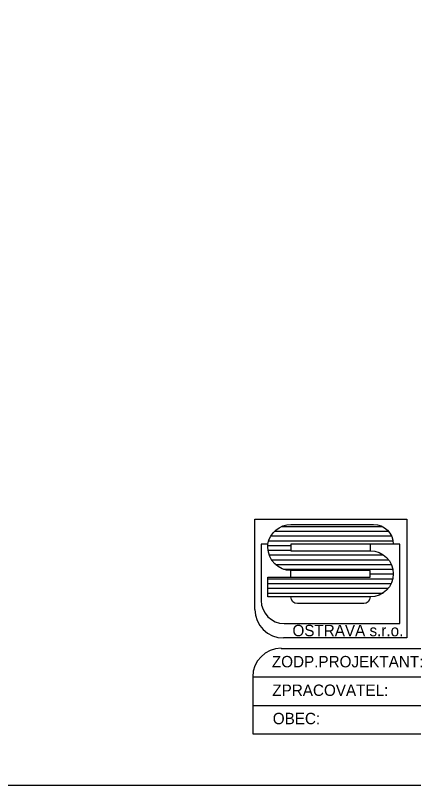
# Model space of a CAD drawing. Extents: x -557942 to -541772, y -1047288 to -1036007.
# Drawn here: x -556692 to -556272, y -1042803 to -1041993 of the extents above; entities that cross this region are included whole.
import ezdxf

# ---------------------------------------------------------------- set-up
doc = ezdxf.new("R2010")
doc.units = 0
doc.layers.add('Vrstva 1', color=7, linetype='Continuous')

msp = doc.modelspace()

# ---------------------------------------------------------------- linework, layer by layer
at = {"layer": 'Vrstva 1'}
for p, q in [((-556418.69, -1042535.45), (-556298.97, -1042535.45)), ((-556418.69, -1042535.45), (-556298.97, -1042535.45)), ((-556411.36, -1042530.45), (-556305.45, -1042530.45)), ((-556411.36, -1042530.45), (-556305.45, -1042530.45)), ((-556422.71, -1042540.45), (-556295.66, -1042540.45)), ((-556422.71, -1042540.45), (-556295.66, -1042540.45)), ((-556425.77, -1042550.45), (-556401.53, -1042550.45)), ((-556425.77, -1042550.45), (-556401.53, -1042550.45)), ((-556424.89, -1042545.45), (-556294.09, -1042545.45)), ((-556424.89, -1042545.45), (-556294.09, -1042545.45)), ((-556425.55, -1042555.45), (-556401.53, -1042555.45)), ((-556425.55, -1042555.45), (-556401.53, -1042555.45)), ((-556424.42, -1042560.45), (-556304.06, -1042560.45)), ((-556424.42, -1042560.45), (-556304.06, -1042560.45)), ((-556422.01, -1042565.45), (-556298.9, -1042565.45)), ((-556422.01, -1042565.45), (-556298.9, -1042565.45)), ((-556417.82, -1042570.45), (-556295.9, -1042570.45)), ((-556417.82, -1042570.45), (-556295.9, -1042570.45)), ((-556409.49, -1042575.45), (-556294.24, -1042575.45)), ((-556409.49, -1042575.45), (-556294.24, -1042575.45)), ((-556425.83, -1042585.45), (-556294.32, -1042585.45)), ((-556425.83, -1042585.45), (-556294.32, -1042585.45)), ((-556318.06, -1042580.45), (-556293.77, -1042580.45)), ((-556318.06, -1042580.45), (-556293.77, -1042580.45)), ((-556425.83, -1042590.45), (-556296.04, -1042590.45)), ((-556425.83, -1042590.45), (-556296.04, -1042590.45)), ((-556425.83, -1042595.45), (-556299.16, -1042595.45)), ((-556425.83, -1042595.45), (-556299.16, -1042595.45)), ((-556425.83, -1042600.45), (-556304.37, -1042600.45)), ((-556425.83, -1042600.45), (-556304.37, -1042600.45)), ((-556411.84, -1042658.67), (-555561.84, -1042658.67)), ((-556411.84, -1042658.67), (-555561.84, -1042658.67)), ((-556441.84, -1042688.67), (-555561.84, -1042688.67)), ((-556441.84, -1042688.67), (-556441.84, -1042748.67)), ((-556441.84, -1042688.67), (-555561.84, -1042688.67)), ((-556441.84, -1042688.67), (-556441.84, -1042748.67)), ((-556441.84, -1042718.67), (-555561.84, -1042718.67)), ((-556441.84, -1042718.67), (-555561.84, -1042718.67)), ((-556441.84, -1042748.67), (-555561.84, -1042748.67)), ((-556441.84, -1042748.67), (-555561.84, -1042748.67))]:
    msp.add_line(p, q, dxfattribs=at)
msp.add_lwpolyline([(-555441.84, -1039561.93), (-555441.84, -1042803.07), (-557941.84, -1042803.07), (-557941.84, -1039561.93)], close=True, dxfattribs=at)
for points in [[(-556439.45, -1042617.77), (-556439.45, -1042522.77), (-556279.45, -1042522.77), (-556279.45, -1042647.77), (-556409.45, -1042647.77)], [(-556439.45, -1042617.77), (-556439.45, -1042522.77), (-556279.45, -1042522.77), (-556279.45, -1042647.77), (-556409.45, -1042647.77)], [(-556318.06, -1042549.17), (-556401.53, -1042549.17), (-556401.53, -1042556.02), (-556318.06, -1042556.02), (-556313.1, -1042556.5), (-556308.53, -1042557.93), (-556304.34, -1042560.22), (-556300.81, -1042563.17), (-556297.86, -1042566.7), (-556295.67, -1042570.89), (-556294.24, -1042575.46), (-556293.76, -1042580.32), (-556294.24, -1042585.18), (-556295.67, -1042589.76), (-556297.86, -1042593.85), (-556300.81, -1042597.47), (-556304.34, -1042600.43), (-556308.53, -1042602.72), (-556313.1, -1042604.14), (-556318.06, -1042604.62), (-556401.53, -1042604.62), (-556425.83, -1042604.62), (-556425.83, -1042583.85), (-556401.53, -1042583.85), (-556318.06, -1042583.85), (-556318.06, -1042576.89), (-556401.53, -1042576.89), (-556406.39, -1042576.42), (-556410.96, -1042574.99), (-556415.06, -1042572.7), (-556418.68, -1042569.75), (-556421.64, -1042566.13), (-556423.92, -1042562.03), (-556425.35, -1042557.45), (-556425.83, -1042552.59), (-556425.73, -1042548.97), (-556424.68, -1042544.59), (-556422.87, -1042540.68), (-556420.39, -1042537.16), (-556417.44, -1042534.2), (-556413.91, -1042531.73), (-556410.1, -1042529.82), (-556405.91, -1042528.68), (-556401.53, -1042528.3), (-556314.63, -1042528.3), (-556310.34, -1042528.68), (-556306.43, -1042529.92), (-556302.91, -1042531.82), (-556299.86, -1042534.39), (-556297.29, -1042537.44), (-556295.38, -1042540.97), (-556294.14, -1042544.88), (-556293.76, -1042549.17), (-556318.06, -1042549.17)], [(-556318.06, -1042549.17), (-556401.53, -1042549.17), (-556401.53, -1042556.02), (-556318.06, -1042556.02), (-556313.1, -1042556.5), (-556308.53, -1042557.93), (-556304.34, -1042560.22), (-556300.81, -1042563.17), (-556297.86, -1042566.7), (-556295.67, -1042570.89), (-556294.24, -1042575.46), (-556293.76, -1042580.32), (-556294.24, -1042585.18), (-556295.67, -1042589.76), (-556297.86, -1042593.85), (-556300.81, -1042597.47), (-556304.34, -1042600.43), (-556308.53, -1042602.72), (-556313.1, -1042604.14), (-556318.06, -1042604.62), (-556401.53, -1042604.62), (-556425.83, -1042604.62), (-556425.83, -1042583.85), (-556401.53, -1042583.85), (-556318.06, -1042583.85), (-556318.06, -1042576.89), (-556401.53, -1042576.89), (-556406.39, -1042576.42), (-556410.96, -1042574.99), (-556415.06, -1042572.7), (-556418.68, -1042569.75), (-556421.64, -1042566.13), (-556423.92, -1042562.03), (-556425.35, -1042557.45), (-556425.83, -1042552.59), (-556425.73, -1042548.97), (-556424.68, -1042544.59), (-556422.87, -1042540.68), (-556420.39, -1042537.16), (-556417.44, -1042534.2), (-556413.91, -1042531.73), (-556410.1, -1042529.82), (-556405.91, -1042528.68), (-556401.53, -1042528.3), (-556314.63, -1042528.3), (-556310.34, -1042528.68), (-556306.43, -1042529.92), (-556302.91, -1042531.82), (-556299.86, -1042534.39), (-556297.29, -1042537.44), (-556295.38, -1042540.97), (-556294.14, -1042544.88), (-556293.76, -1042549.17), (-556318.06, -1042549.17)], [(-556286.71, -1042632.54), (-556286.71, -1042549.07), (-556293.76, -1042549.07), (-556318.06, -1042549.07), (-556318.06, -1042556.02), (-556313.1, -1042556.5), (-556308.53, -1042557.93), (-556304.34, -1042560.22), (-556300.81, -1042563.17), (-556297.86, -1042566.7), (-556295.67, -1042570.89), (-556294.24, -1042575.46), (-556293.76, -1042580.32), (-556294.24, -1042585.18), (-556295.67, -1042589.76), (-556297.86, -1042593.85), (-556300.81, -1042597.47), (-556304.34, -1042600.43), (-556308.53, -1042602.72), (-556313.1, -1042604.14), (-556318.06, -1042604.62), (-556318.63, -1042607.38), (-556320.06, -1042609.58), (-556322.25, -1042611.1), (-556324.92, -1042611.67), (-556394.57, -1042611.67), (-556397.34, -1042611.1), (-556399.53, -1042609.58), (-556400.96, -1042607.38), (-556401.53, -1042604.62), (-556425.83, -1042604.62), (-556425.83, -1042583.75), (-556401.53, -1042583.75), (-556401.53, -1042576.89), (-556406.39, -1042576.42), (-556410.96, -1042574.99), (-556415.06, -1042572.7), (-556418.68, -1042569.75), (-556421.64, -1042566.13), (-556423.92, -1042562.03), (-556425.35, -1042557.45), (-556425.83, -1042552.59), (-556425.73, -1042548.97), (-556432.88, -1042549.07), (-556432.88, -1042608.24), (-556432.4, -1042613.1), (-556430.97, -1042617.67), (-556428.69, -1042621.77), (-556425.73, -1042625.4), (-556422.11, -1042628.35), (-556418.01, -1042630.63), (-556413.44, -1042632.06), (-556408.58, -1042632.54), (-556408.39, -1042632.54), (-556286.71, -1042632.54)], [(-556286.71, -1042632.54), (-556286.71, -1042549.07), (-556293.76, -1042549.07), (-556318.06, -1042549.07), (-556318.06, -1042556.02), (-556313.1, -1042556.5), (-556308.53, -1042557.93), (-556304.34, -1042560.22), (-556300.81, -1042563.17), (-556297.86, -1042566.7), (-556295.67, -1042570.89), (-556294.24, -1042575.46), (-556293.76, -1042580.32), (-556294.24, -1042585.18), (-556295.67, -1042589.76), (-556297.86, -1042593.85), (-556300.81, -1042597.47), (-556304.34, -1042600.43), (-556308.53, -1042602.72), (-556313.1, -1042604.14), (-556318.06, -1042604.62), (-556318.63, -1042607.38), (-556320.06, -1042609.58), (-556322.25, -1042611.1), (-556324.92, -1042611.67), (-556394.57, -1042611.67), (-556397.34, -1042611.1), (-556399.53, -1042609.58), (-556400.96, -1042607.38), (-556401.53, -1042604.62), (-556425.83, -1042604.62), (-556425.83, -1042583.75), (-556401.53, -1042583.75), (-556401.53, -1042576.89), (-556406.39, -1042576.42), (-556410.96, -1042574.99), (-556415.06, -1042572.7), (-556418.68, -1042569.75), (-556421.64, -1042566.13), (-556423.92, -1042562.03), (-556425.35, -1042557.45), (-556425.83, -1042552.59), (-556425.73, -1042548.97), (-556432.88, -1042549.07), (-556432.88, -1042608.24), (-556432.4, -1042613.1), (-556430.97, -1042617.67), (-556428.69, -1042621.77), (-556425.73, -1042625.4), (-556422.11, -1042628.35), (-556418.01, -1042630.63), (-556413.44, -1042632.06), (-556408.58, -1042632.54), (-556408.39, -1042632.54), (-556286.71, -1042632.54)]]:
    msp.add_lwpolyline(points, dxfattribs=at)
for centre, start, end in [((-556409.45, -1042617.77), 180, 270), ((-556409.45, -1042617.77), 180, 270), ((-556411.84, -1042688.66), 90, 180), ((-556411.84, -1042688.66), 90, 180)]:
    msp.add_arc(centre, 30, start, end, dxfattribs=at)

# ---------------------------------------------------------------- texts
for s, p in [('OSTRAVA s.r.o.', (-556399.95, -1042645.94)), ('OSTRAVA s.r.o.', (-556399.95, -1042645.94)), ('ZODP.PROJEKTANT:', (-556421.63, -1042678.66)), ('ZPRACOVATEL:', (-556421.15, -1042708.73)), ('ZPRACOVATEL:', (-556421.15, -1042708.73)), ('OBEC:', (-556420.68, -1042738.5))]:
    msp.add_text(s, height=12, dxfattribs=at).set_placement(p)

doc.saveas('drawing.dxf')
